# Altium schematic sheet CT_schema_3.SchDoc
size 313 x 185 mm
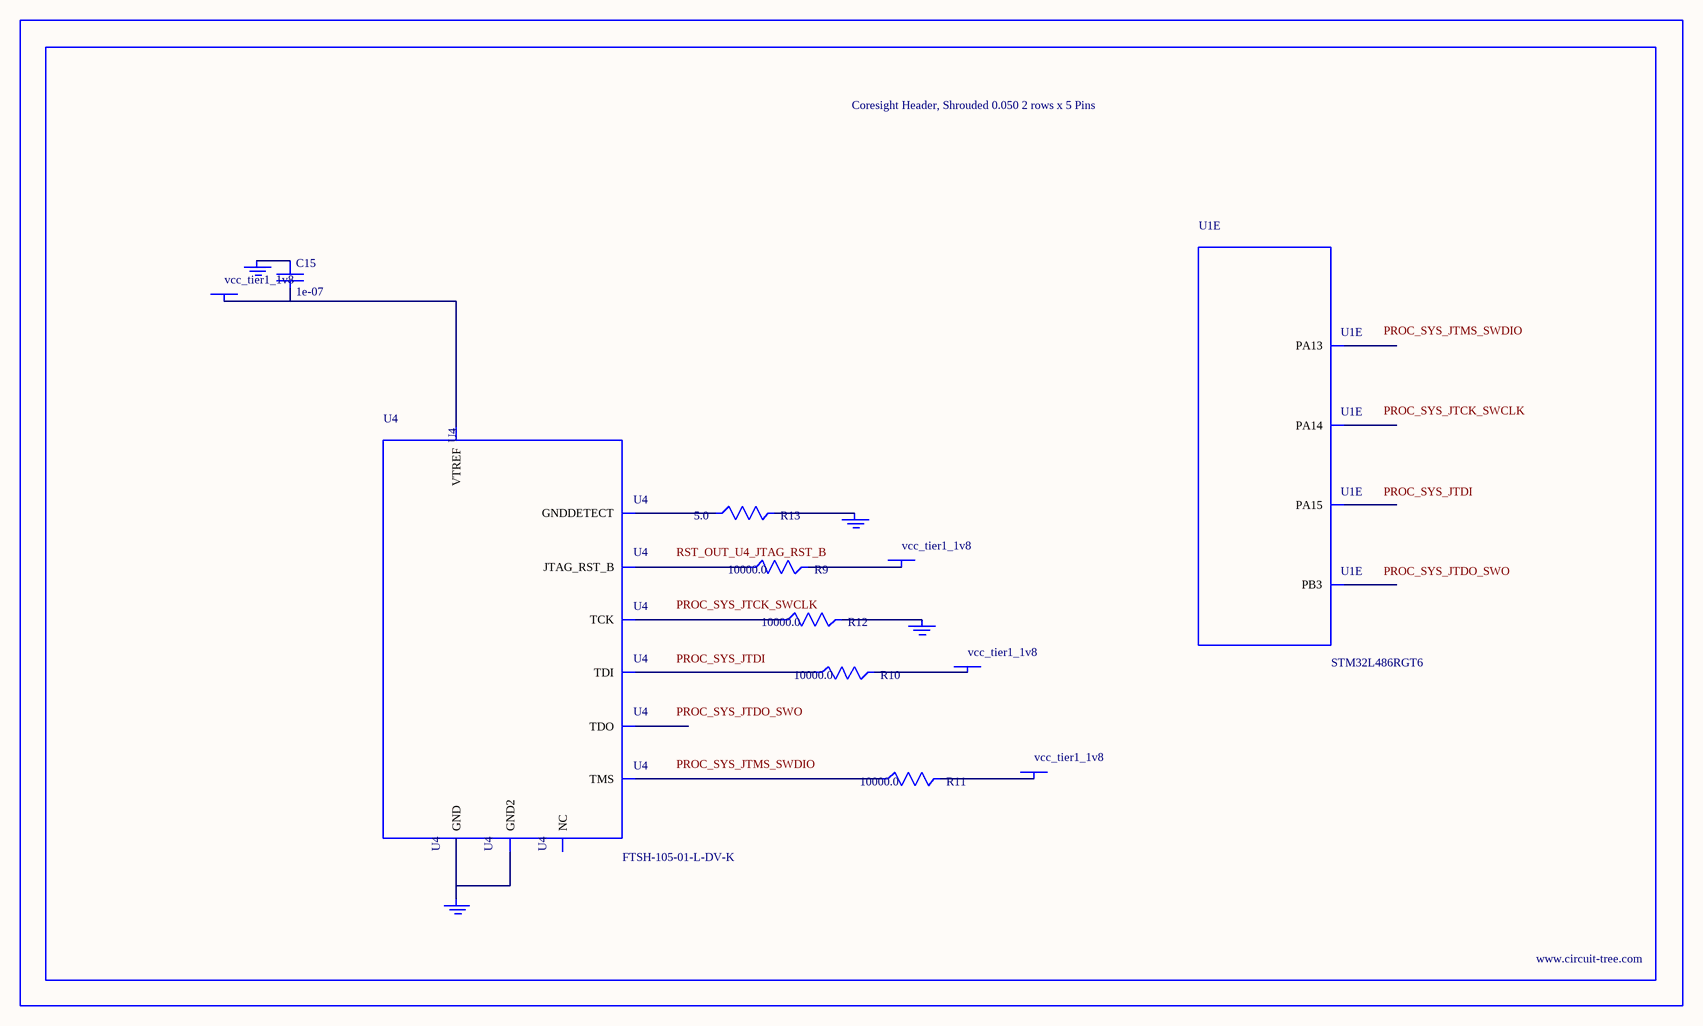
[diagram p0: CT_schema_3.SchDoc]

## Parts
BORDER2  (no value)
C15  1e-07  [C0402]
GND_INSTANCE_2_0  (no value)
GND_INSTANCE_2_1  (no value)
GND_INSTANCE_2_2  (no value)
GND_INSTANCE_2_3  (no value)
POWER_INSTANCE_2_0  vcc_tier1_1v8
POWER_INSTANCE_2_1  vcc_tier1_1v8
POWER_INSTANCE_2_2  vcc_tier1_1v8
POWER_INSTANCE_2_3  vcc_tier1_1v8
R9  10000.0  [R0603]
R10  10000.0  [R0603]
R11  10000.0  [R0603]
R12  10000.0  [R0603]
R13  5.0  [R0603]
U1  STM32L486RGT6  [LQFP64]  (part E of 7)
U4  FTSH-105-01-L-DV-K  [SAMTEC_FTSH-105-01-L-DV-K]

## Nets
NetC15_1: C15.1 GND_INSTANCE_2_0.0(GND)
NetC15_2: C15.2 POWER_INSTANCE_2_0.0(PWR) U4.1(VTREF)
NetGND_INSTANCE_2_1_0: GND_INSTANCE_2_1.0(GND) R12.2
NetGND_INSTANCE_2_2_0: GND_INSTANCE_2_2.0(GND) R13.2
NetGND_INSTANCE_2_3_0: GND_INSTANCE_2_3.0(GND) U4.3(GND) U4.5(GND2)
NetPOWER_INSTANCE_2_1_0: POWER_INSTANCE_2_1.0(PWR) R11.2
NetPOWER_INSTANCE_2_2_0: POWER_INSTANCE_2_2.0(PWR) R10.2
NetPOWER_INSTANCE_2_3_0: POWER_INSTANCE_2_3.0(PWR) R9.2
NetR9_1: R9.1 U4.10(JTAG_RST_B)
NetR10_1: R10.1 U4.8(TDI)
NetR11_1: R11.1 U4.2(TMS)
NetR12_1: R12.1 U4.4(TCK)
NetR13_1: R13.1 U4.9(GNDDETECT)

Not connected (* = marked no-connect by the designer): U1 46(PA13) 49(PA14) 50(PA15) 55(PB3); U4 6(TDO) 7(NC)

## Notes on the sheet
- Labels drawn without touching a wire or pin: PROC_SYS_JTCK_SWCLK, PROC_SYS_JTDI, PROC_SYS_JTDO_SWO, PROC_SYS_JTMS_SWDIO, RST_OUT_U4_JTAG_RST_B

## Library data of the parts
BORDER2 = BORDER_PAGE2
C15 = C0402C104K3RACTU
GND_INSTANCE_2_0-GND_INSTANCE_2_3 = GND
POWER_INSTANCE_2_0-POWER_INSTANCE_2_3 = PWR
R9-R12 = RC0603JR-0710KL
R13 = ERJ-3GEYJ5R1V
